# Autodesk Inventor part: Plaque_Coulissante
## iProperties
Created: 2008-12
Part Number: Plaque_Coulissante
Document SubType Name: Modeling
Designer: claivier
Author: claivier
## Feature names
1. Extrusion1
2. Congé1 [Fillet]
3. Coque1
4. Extrusion3
5. Extrusion4
6. Extrusion5
7. Extrusion6
8. Perçage1 [Hole]
9. Extrusion7
10. Miroir2 [Mirror]
11. Chanfrein1 [Chamfer]
